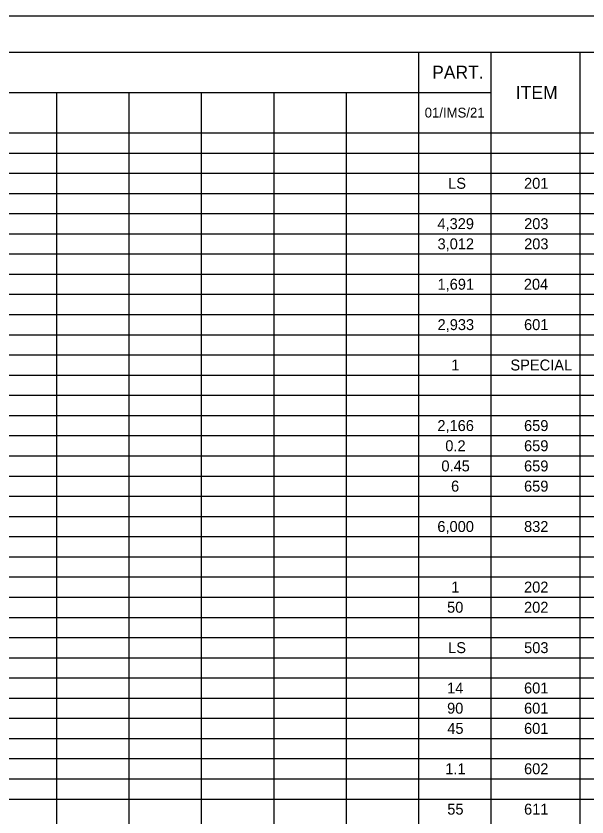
# Model space of a CAD drawing. Extents: x 0 to 34, y 0 to 22.
# Drawn here: x 8.98 to 16.9, y 10.89 to 22 of the extents above; entities that cross this region are included whole.
import ezdxf

# ---------------------------------------------------------------- set-up
doc = ezdxf.new("R2010")
doc.units = 0
for name, color, linetype in [('SH_Border', 7, 'Continuous'), ('SH_Cut_Line', 7, 'Continuous'), ('SH_Text', 7, 'Continuous')]:
    doc.layers.add(name, color=color, linetype=linetype)

msp = doc.modelspace()

# ---------------------------------------------------------------- linework, layer by layer
at = {"layer": 'SH_Border'}
msp.add_lwpolyline([(1.5, 21.5), (33.5, 21.5), (33.5, 0.5), (1.5, 0.5)], close=True, dxfattribs=at)
at = {"layer": 'SH_Cut_Line'}
msp.add_lwpolyline([(0, 0), (34, 0), (34, 22), (0, 22)], close=True, dxfattribs=at)
at = {"layer": 'SH_Text'}
for p, q in [((1.5, 21.5), (31.888, 21.5)), ((14.561, 21.5), (14.561, 0.5)), ((15.566, 21.5), (15.566, 0.5)), ((16.801, 21.5), (16.801, 0.5)), ((1.5, 20.94), (15.566, 20.94)), ((9.538, 20.94), (9.538, 0.5)), ((10.542, 20.94), (10.542, 0.5)), ((11.547, 20.94), (11.547, 0.5)), ((12.552, 20.94), (12.552, 0.5)), ((13.556, 20.94), (13.556, 0.5)), ((1.5, 20.38), (31.888, 20.38)), ((1.5, 20.1), (31.888, 20.1)), ((1.5, 19.82), (31.888, 19.82)), ((1.5, 19.54), (31.888, 19.54)), ((1.5, 19.26), (31.888, 19.26)), ((1.5, 18.98), (31.888, 18.98)), ((1.5, 18.7), (31.888, 18.7)), ((1.5, 18.42), (31.888, 18.42)), ((1.5, 18.14), (31.888, 18.14)), ((1.5, 17.86), (31.888, 17.86)), ((1.5, 17.58), (31.888, 17.58)), ((1.5, 17.3), (31.888, 17.3)), ((1.5, 17.02), (31.888, 17.02)), ((1.5, 16.74), (31.888, 16.74)), ((1.5, 16.46), (31.888, 16.46)), ((1.5, 16.18), (31.888, 16.18)), ((1.5, 15.9), (31.888, 15.9)), ((1.5, 15.62), (31.888, 15.62)), ((1.5, 15.34), (31.888, 15.34)), ((1.5, 15.06), (31.888, 15.06)), ((1.5, 14.78), (31.888, 14.78)), ((1.5, 14.5), (31.888, 14.5)), ((1.5, 14.22), (31.888, 14.22)), ((1.5, 13.94), (31.888, 13.94)), ((1.5, 13.66), (31.888, 13.66)), ((1.5, 13.38), (31.888, 13.38)), ((1.5, 13.1), (31.888, 13.1)), ((1.5, 12.82), (31.888, 12.82)), ((1.5, 12.54), (31.888, 12.54)), ((1.5, 12.26), (31.888, 12.26)), ((1.5, 11.98), (31.888, 11.98)), ((1.5, 11.7), (31.888, 11.7)), ((1.5, 11.42), (31.888, 11.42)), ((1.5, 11.14), (31.888, 11.14))]:
    msp.add_line(p, q, dxfattribs=at)

# ---------------------------------------------------------------- texts
for s, height, p in [('PART.', 0.1818, (14.75, 21.129)), ('ITEM', 0.1818, (15.912, 20.849)), ('01/IMS/21', 0.1364, (14.647, 20.592)), ('LS', 0.1515, (14.973, 19.604)), ('201', 0.1515, (16.026, 19.604)), ('4,329', 0.1515, (14.824, 19.044)), ('203', 0.1515, (16.027, 19.044)), ('3,012', 0.1515, (14.825, 18.764)), ('203', 0.1515, (16.027, 18.764)), ('1,691', 0.1515, (14.825, 18.204)), ('204', 0.1515, (16.023, 18.204)), ('2,933', 0.1515, (14.826, 17.644)), ('601', 0.1515, (16.026, 17.644)), ('1', 0.152, (15.015, 17.084)), ('SPECIAL', 0.1515, (15.837, 17.084)), ('2,166', 0.1515, (14.823, 16.244)), ('659', 0.1515, (16.026, 16.244)), ('0.2', 0.1515, (14.933, 15.964)), ('659', 0.1515, (16.026, 15.964)), ('0.45', 0.1515, (14.879, 15.684)), ('659', 0.1515, (16.026, 15.684)), ('6', 0.152, (15.013, 15.404)), ('659', 0.1515, (16.026, 15.404)), ('6,000', 0.1515, (14.823, 14.844)), ('832', 0.1515, (16.026, 14.844)), ('1', 0.152, (15.015, 14.004)), ('202', 0.1515, (16.026, 14.004)), ('50', 0.1515, (14.958, 13.724)), ('202', 0.1515, (16.026, 13.724)), ('LS', 0.1515, (14.973, 13.164)), ('503', 0.1515, (16.027, 13.164)), ('14', 0.1515, (14.958, 12.604)), ('601', 0.1515, (16.026, 12.604)), ('90', 0.1515, (14.958, 12.324)), ('601', 0.1515, (16.026, 12.324)), ('45', 0.1515, (14.961, 12.044)), ('601', 0.1515, (16.026, 12.044)), ('1.1', 0.1515, (14.933, 11.484)), ('602', 0.1515, (16.026, 11.484)), ('55', 0.1515, (14.961, 10.924)), ('611', 0.1515, (16.026, 10.924))]:
    msp.add_text(s, height=height, dxfattribs=at).set_placement(p)

doc.saveas('drawing.dxf')
